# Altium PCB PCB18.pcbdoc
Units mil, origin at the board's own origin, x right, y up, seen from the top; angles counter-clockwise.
Board outline 1050 x 1540 mil, 2 copper layers (Top Layer, Bottom Layer); 7 components, 3 nets, 17 pads, 28 vias.
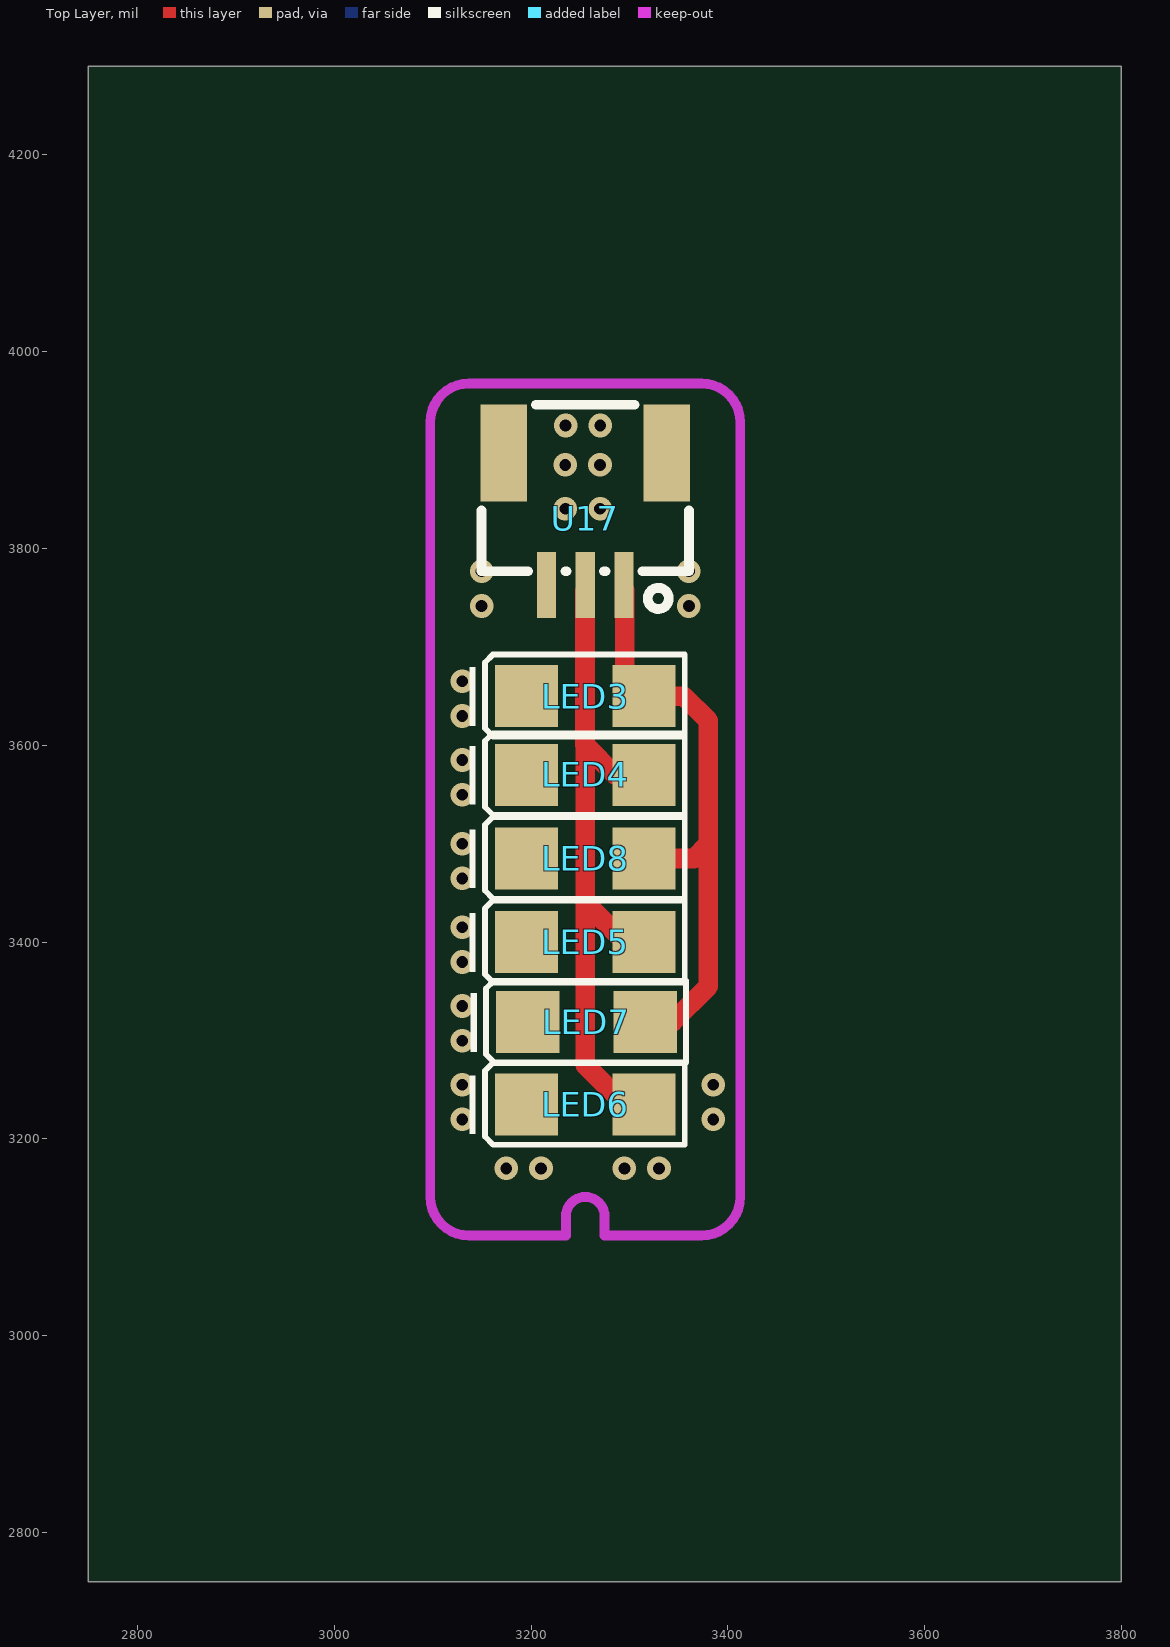
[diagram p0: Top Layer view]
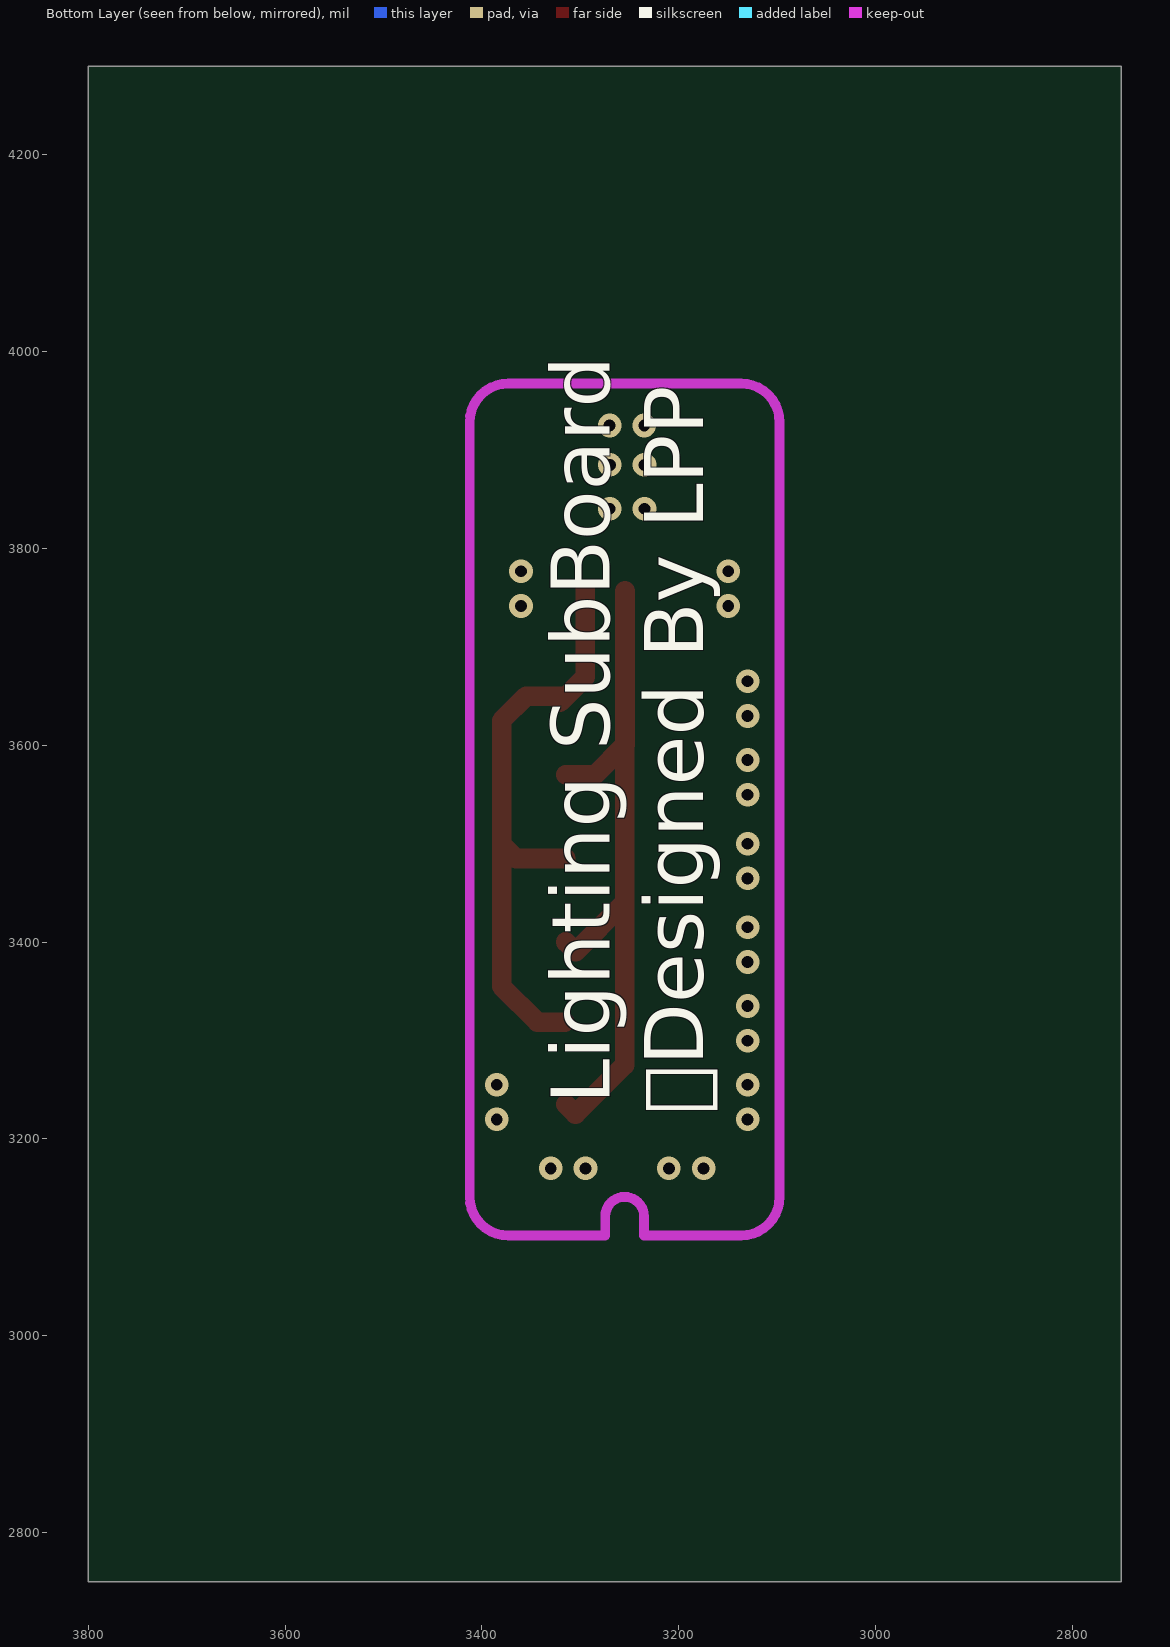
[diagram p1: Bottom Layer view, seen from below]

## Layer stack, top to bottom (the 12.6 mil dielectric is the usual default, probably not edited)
Top Layer: signal copper (thickness not stored)
Dielectric: dielectric 12.6, FR-4, Dk 4.8
Bottom Layer: signal copper (thickness not stored)

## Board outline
3800,2750 2750,2750 2750,4290 3800,4290

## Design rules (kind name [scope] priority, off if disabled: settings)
BoardOutlineClearance copperThickness1oz [All] p0: genericclearance=10 ignorepadtopadclearanceinfootprint=FALSE except(0: Arc-SplitContinuation Track-SplitContinuation SMDPad-SplitContinuation THPad-SplitContinuation Via-SplitContinuation Fill-SplitContinuation Poly-SplitContinuation Region-SplitContinuation Text-SplitContinuation; 6: Track-CutoutEdge SMDPad-CutoutEdge THPad-CutoutEdge Via-CutoutEdge Region-CutoutEdge; 11.8: Track-OutlineEdge SMDPad-OutlineEdge THPad-OutlineEdge Via-OutlineEdge Fill-OutlineEdge Region-OutlineEdge Poly-OutlineEdge Text-OutlineEdge Fill-CutoutEdge)
BoardOutlineClearance copperThickness2oz [All] p0: genericclearance=10 ignorepadtopadclearanceinfootprint=FALSE except(0: Arc-SplitContinuation Track-SplitContinuation SMDPad-SplitContinuation THPad-SplitContinuation Via-SplitContinuation Fill-SplitContinuation Poly-SplitContinuation Region-SplitContinuation Text-SplitContinuation; 6: Track-CutoutEdge SMDPad-CutoutEdge THPad-CutoutEdge Via-CutoutEdge Region-CutoutEdge; 11.8: Track-OutlineEdge SMDPad-OutlineEdge THPad-OutlineEdge Via-OutlineEdge Fill-OutlineEdge Region-OutlineEdge Poly-OutlineEdge Text-OutlineEdge Fill-CutoutEdge)
Clearance copperThickness1oz [(InNet('SUBGND') OR InNet('$1N370') OR InNet('$1N373'))] p1: gap=7 ignorepadtopadclearanceinfootprint=FALSE except(4: Track-Track; 6: Track-SMDPad SMDPad-SMDPad Track-THPad SMDPad-THPad THPad-THPad Track-Via SMDPad-Via THPad-Via Via-Via SMDPad-Fill THPad-Fill Via-Fill Fill-Fill Track-Region SMDPad-Region THPad-Region Via-Region Region-Region Track-Poly SMDPad-Poly THPad-Poly Via-Poly Fill-Poly Region-Poly Poly-Poly Track-Text SMDPad-Text THPad-Text Via-Text Fill-Text Region-Text Poly-Text Text-Text; 6.9: Track-Hole SMDPad-Hole THPad-Hole Via-Hole Fill-Hole Region-Hole Poly-Hole Text-Hole Sheet-Hole; 11.8: Track-Fill Fill-Region Track-Sheet SMDPad-Sheet THPad-Sheet Via-Sheet Fill-Sheet Region-Sheet Poly-Sheet Text-Sheet)
Clearance copperThickness2oz [All] p1: gap=7 ignorepadtopadclearanceinfootprint=FALSE except(6: Track-SMDPad SMDPad-SMDPad Track-THPad SMDPad-THPad THPad-THPad Track-Via SMDPad-Via THPad-Via Via-Via SMDPad-Fill THPad-Fill Via-Fill Fill-Fill Track-Region SMDPad-Region THPad-Region Via-Region Region-Region Track-Poly SMDPad-Poly THPad-Poly Via-Poly Fill-Poly Region-Poly Poly-Poly Track-Text SMDPad-Text THPad-Text Via-Text Fill-Text Region-Text Poly-Text Text-Text; 6.9: Track-Hole SMDPad-Hole THPad-Hole Via-Hole Fill-Hole Region-Hole Poly-Hole Text-Hole Sheet-Hole; 8: Track-Track; 11.8: Track-Fill Fill-Region Track-Sheet SMDPad-Sheet THPad-Sheet Via-Sheet Fill-Sheet Region-Sheet Poly-Sheet Text-Sheet)
DiffPairsRouting differentialPair [All] p1: maxuncoupledlength=10 minlimit=5.9843 maxlimit=5.9843 mostfreqgap=5.9843 toplayer_minwidth=5 toplayer_prefwidth=10 toplayer_maxwidth=100 bottomlayer_minwidth=5 bottomlayer_prefwidth=10 bottomlayer_maxwidth=100
PasteMaskExpansion pasteMaskExpansion [All] p1: expansion=0
PlaneConnect innerPlane [All] p1: planeconnectstyle=Relief reliefexpansion=20 reliefentries=4 reliefconductorwidth=10 reliefairgap=10
PolygonConnect copperRegion [All] p1: connectstyle=Direct reliefentries=4 reliefconductorwidth=10 polygonreliefangle="90 Angle" airgapwidth=10
RoutingVias viaSize [All] p1: viastyle="Through Hole" holewidth=12.0078 minholewidth=11.811 maxholewidth=248.0314 width=24.0158 minwidth=19.685 maxwidth=393.7008
SolderMaskExpansion solderMaskExpansion [All] p1: useseparateexpansions=TRUE expansion=2.0079 expansionbottom=2.0079
Width copperThickness1oz [All] p1: maxlimit=100 minlimit=5 preferedwidth=10
Width copperThickness2oz [All] p1: maxlimit=100 minlimit=8 preferedwidth=10

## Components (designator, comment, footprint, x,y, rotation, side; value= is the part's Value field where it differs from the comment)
LED3 "SZYY1206O" LED1206-RD_ORANGE 3255,3650 r0 top
LED4 "SZYY1206B" LED1206-RD_BLUE 3255,3570 r0 top
LED5 "SZYY1206B" LED1206-RD_BLUE 3255,3400 r0 top
LED6 "SZYY1206B" LED1206-RD_BLUE 3255,3235 r0 top
LED7 "SZYY1206O" LED1206-RD_ORANGE 3256.12,3318.58 r0 top
LED8 "SZYY1206O" LED1206-RD_ORANGE 3255,3485 r0 top
U17 "WAFER-SH1.0-3PWB" CONN-SMD_3P-P1.00_WAFER-SH1.0-3PWB 3255,3830 r180 top

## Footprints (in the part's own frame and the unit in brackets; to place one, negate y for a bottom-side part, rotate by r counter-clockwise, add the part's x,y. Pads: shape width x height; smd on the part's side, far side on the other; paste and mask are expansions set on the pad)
CONN-SMD_3P-P1.00_WAFER-SH1.0-3PWB [mm]
  rect 0.5x1.7 smd: 1(-1,1.7) 2(0,1.7) 3(1,1.7)
  rect 1.2x2.5 smd: 4(-2.1,-1.7) 5(2.1,-1.7)
  silkscreen extent -2.68,-2.95 2.67,2.32
LED1206-RD_BLUE [mm]
  rect 1.635x1.6 smd: 1(-1.517,0) 2(1.517,0)
  silkscreen extent -2.99,-1.04 2.57,1.07
LED1206-RD_ORANGE [mm]
  rect 1.635x1.6 smd: 1(-1.517,0) 2(1.517,0)
  silkscreen extent -2.99,-1.04 2.57,1.07

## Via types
v1: diameter 24.02, hole 12.01, Top Layer to Bottom Layer, 28 vias

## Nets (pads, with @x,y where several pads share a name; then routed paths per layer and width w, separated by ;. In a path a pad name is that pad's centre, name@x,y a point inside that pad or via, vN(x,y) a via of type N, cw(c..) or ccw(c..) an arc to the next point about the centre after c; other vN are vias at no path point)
$1N370: LED3.2 LED7.2 LED8.2 U17.1 | length 621.1
  Top Layer w20: U17.1@3295,3757.8 3295,3669.44 LED3.2@3320.86,3643.58 ; LED8.2 3365.3,3485 3380,3499.7 ; LED3.2 3355,3650 3380,3625 3380,3499.7 ; LED7.2 3343.58,3318.58 3380,3355 3380,3499.7
$1N373: LED4.2 LED5.2 LED6.2 U17.2 | length 722.7
  Top Layer w20: 3254.7,3600.34 U17.2@3254.7,3756.87 ; LED6.2 3304.87,3225.13 3255,3275 3255,3440 ; LED5.2 3304.87,3390.13 3255,3440 ; LED4.2 3285.04,3570 3255,3600.04 3255,3440
SUBGND: LED3.1 LED4.1 LED5.1 LED6.1 LED7.1 LED8.1 U17.3 U17.4 U17.5
  other v1: 3174.75,3170 3210,3170 3294.75,3170 3330,3170 3130,3219.75 3385,3219.75 3130,3255 3385,3255 3130,3299.75 3130,3335 3130,3379.75 3130,3415 3130,3464.75 3130,3500 3130,3549.75 3130,3585 3130,3629.75 3130,3665 3149.69,3741.6 3360.32,3741.6 3149.69,3776.85 3360.32,3776.85 3234.79,3840.37 3270.04,3840.37 3234.75,3885 3270,3885 3235,3925 3270.25,3925

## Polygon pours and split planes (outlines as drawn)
SUBGND on Top Layer (solid, remove dead copper, pour order 0): 3000,4040 3465,4040 3465,3075 3000,3075
SUBGND on Bottom Layer (solid, remove dead copper, pour order 2): 3070,3995 3550,3995 3550,3000 3070,3000

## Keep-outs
Board Outline Layer:
  lines w10: 3235.32,3101.65 3136.89,3101.65 cw(c3136.89,3141.02) 3097.52,3141.02 3097.52,3928.43 cw(c3136.89,3928.43) 3136.89,3967.8 3373.11,3967.8 cw(c3373.11,3928.43) 3412.48,3928.43 3412.48,3141.02 cw(c3373.11,3141.02) 3373.11,3101.65 3274.69,3101.65 ; 3235.32,3101.85 3235.32,3121.34 cw(c3255,3121.34) 3255,3141.02 cw(c3255,3121.34) 3274.69,3121.34 3274.69,3102.73

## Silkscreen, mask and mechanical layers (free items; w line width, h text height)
Bottom Silkscreen Layer:
  text "Lighting SubBoard" at 3270,3235 h60 r270
  text "Designed By LPP" at 3175,3225 h60 r270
